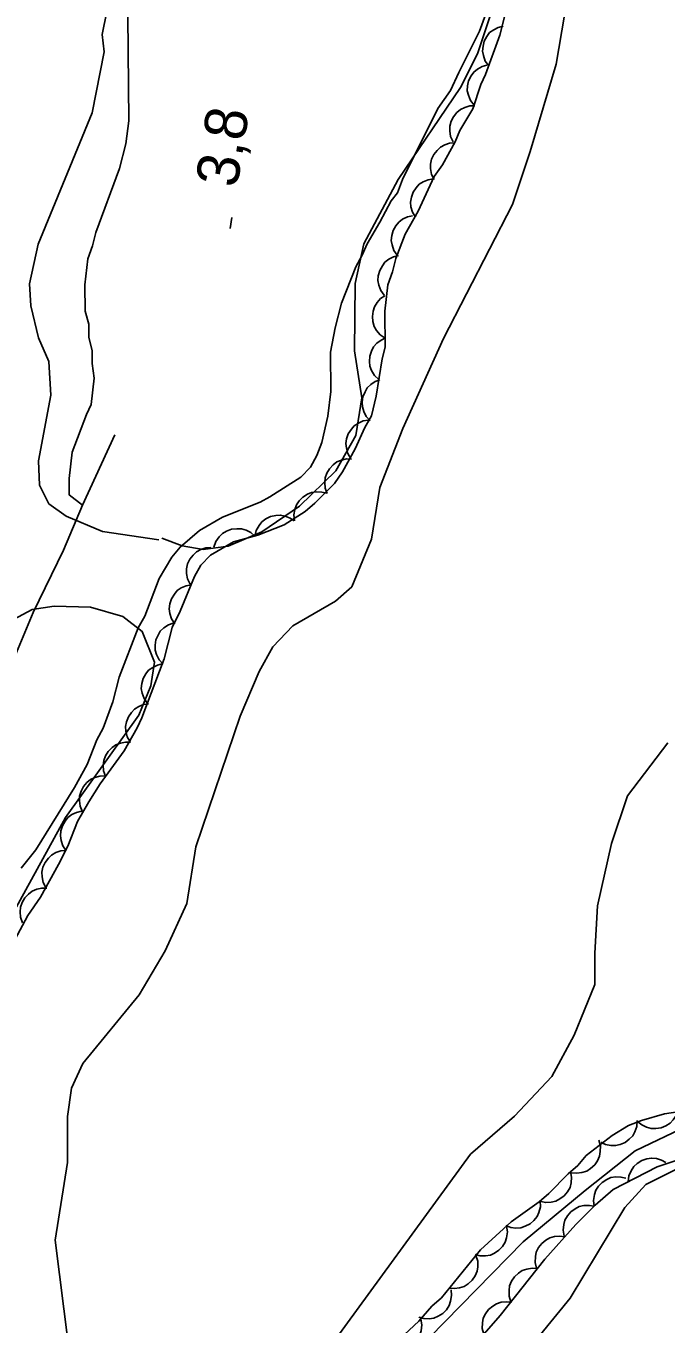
# Model space of a CAD drawing. Extents: x 282461 to 284471, y 5554090 to 5557646.
# Drawn here: x 283743.9 to 283789.4, y 5555319.8 to 5555412 of the extents above; entities that cross this region are included whole.
import ezdxf

# ---------------------------------------------------------------- set-up
doc = ezdxf.new("R2010")
doc.units = 0
for name, color, linetype in [('Niveau 1', 7, 'Continuous'), ('Niveau 2', 7, 'Continuous'), ('Niveau 22', 7, 'Continuous'), ('Niveau 3', 7, 'Continuous'), ('Niveau 44', 7, 'Continuous'), ('Niveau 7', 7, 'Continuous')]:
    doc.layers.add(name, color=color, linetype=linetype)

msp = doc.modelspace()

# ---------------------------------------------------------------- linework, layer by layer
at = {"layer": 'Niveau 1'}
for points in [[(283783.14, 5555418.61), (283781.56, 5555409.27), (283779.71, 5555403.07), (283778.46, 5555399.31), (283773.56, 5555389.8), (283770.67, 5555383.41), (283769.02, 5555379.22), (283768.44, 5555375.55), (283767.05, 5555372.17), (283765.87, 5555371.15), (283762.84, 5555369.4), (283761.44, 5555367.9), (283760.46, 5555366.14), (283759.12, 5555362.98), (283755.96, 5555353.7), (283755.32, 5555349.67), (283753.78, 5555346.33), (283751.93, 5555343.2), (283747.93, 5555338.31), (283747.14, 5555336.56), (283746.84, 5555334.55), (283746.84, 5555331.3), (283745.98, 5555325.79), (283746.9, 5555318.46)], [(283789.48, 5555361.08), (283786.61, 5555357.33), (283785.48, 5555353.95), (283784.48, 5555349.52), (283784.29, 5555346.15), (283784.31, 5555343.94), (283782.84, 5555340.33), (283781.24, 5555337.41), (283778.59, 5555334.59), (283775.48, 5555331.88), (283765.07, 5555317.64)], [(283780.44, 5555319.09), (283782.55, 5555321.65), (283786.43, 5555328.09), (283787.92, 5555329.73), (283792.36, 5555331.94), (283796.89, 5555332.28), (283799.21, 5555331.92), (283803.28, 5555330.44), (283804.08, 5555329.12), (283804, 5555326.4), (283802.31, 5555319.82)]]:
    msp.add_lwpolyline(points, dxfattribs=at)
at = {"layer": 'Niveau 2'}
for points in [[(283753.34, 5555375.49), (283749.33, 5555376.09), (283746.75, 5555377.17), (283745.52, 5555378.06), (283744.86, 5555379.38), (283744.78, 5555381.1), (283745.67, 5555385.76), (283745.53, 5555388.17), (283744.78, 5555389.84), (283744.24, 5555392.12), (283744.14, 5555393.67), (283744.77, 5555396.5), (283748.61, 5555405.81), (283749.45, 5555410.14), (283749.32, 5555411.37), (283750.68, 5555418.17)], [(283777.95, 5555416), (283775.96, 5555409.99), (283774.77, 5555407.61), (283770.33, 5555401.09), (283767.89, 5555396.51), (283767.28, 5555393.7), (283767.24, 5555388.92), (283767.76, 5555385.59), (283767.33, 5555382.91), (283765.9, 5555380.39), (283763.32, 5555377.88), (283760.65, 5555376.07), (283758.25, 5555375.06), (283756.49, 5555374.82), (283755, 5555375.07), (283753.55, 5555375.62)], [(283743.08, 5555349.18), (283746.71, 5555355.78), (283751.92, 5555363.05), (283752.77, 5555365.14), (283753.03, 5555366.81), (283752.15, 5555369), (283750.78, 5555370.06), (283748.48, 5555370.73), (283745.9, 5555370.8), (283744.33, 5555370.55), (283741.36, 5555368.96)]]:
    msp.add_lwpolyline(points, dxfattribs=at)
at = {"layer": 'Niveau 22'}
for points in [[(283750.2, 5555382.95), (283747.9, 5555377.95), (283746.56, 5555374.77), (283744.4, 5555370.33), (283741.9, 5555364.37), (283738.37, 5555352.1), (283733.72, 5555335.92), (283726.74, 5555314), (283724.74, 5555305.03), (283723.2, 5555297.46), (283722.89, 5555293.62), (283718.97, 5555278.88), (283718.11, 5555273.83)], [(283861.57, 5555341.68), (283858.39, 5555340.93), (283855.1, 5555340.42), (283852.52, 5555340.5), (283847.8, 5555340.85), (283842.97, 5555339.89), (283840.1, 5555338.96), (283836.9, 5555337.5), (283831.65, 5555335.94), (283825.53, 5555334.84), (283821.37, 5555334.21), (283813.14, 5555335.8), (283808.66, 5555336.35), (283804.55, 5555336.14), (283801.01, 5555335.82), (283795.13, 5555335.12), (283790.93, 5555333.93), (283787.16, 5555332.13), (283783.61, 5555329.3), (283779.22, 5555325.65), (283772.56, 5555318.87)]]:
    msp.add_lwpolyline(points, dxfattribs=at)
at = {"layer": 'Niveau 3'}
msp.add_line((283758.41, 5555397.59), (283758.53, 5555398.38), dxfattribs=at)
at = {"layer": 'Niveau 44'}
for points in [[(283743.11, 5555347.09), (283744.03, 5555348.84), (283744.94, 5555350.13), (283746.2, 5555352.46), (283746.88, 5555353.75), (283747.56, 5555355.5), (283748.36, 5555356.9), (283749.16, 5555358.18), (283750.88, 5555360.52), (283751.79, 5555362.16), (283752.13, 5555362.86), (283753.72, 5555367.06), (283754.27, 5555369.27), (283754.84, 5555370.44), (283755.86, 5555372.89), (283756.32, 5555373.7), (283757.01, 5555374.41), (283758.63, 5555375.36), (283760.37, 5555375.84), (283762.23, 5555376.56), (283763.73, 5555377.5), (283764.42, 5555378.09), (283765.8, 5555379.5), (283766.38, 5555380.32), (283767.29, 5555381.95), (283767.97, 5555383.47), (283768.43, 5555384.29), (283768.76, 5555385.69), (283769.2, 5555388.36), (283769.42, 5555389.18), (283769.39, 5555391.73), (283769.6, 5555393.59), (283769.94, 5555394.53), (283770.17, 5555395.46), (283770.84, 5555397.21), (283771.76, 5555398.84), (283772.9, 5555401.29), (283773.47, 5555402.11), (283774.38, 5555403.75), (283774.72, 5555404.57), (283775.64, 5555406.09), (283776.2, 5555407.83), (283776.54, 5555408.53), (283777.56, 5555411.33), (283778.67, 5555415.76)], [(283776.77, 5555409.15), (283776.52, 5555409.49), (283776.39, 5555409.88), (283776.33, 5555410.2), (283776.36, 5555410.55), (283776.45, 5555410.91), (283776.64, 5555411.24), (283776.83, 5555411.51), (283777.12, 5555411.71), (283777.44, 5555411.88), (283777.79, 5555411.97)], [(283775.72, 5555406.35), (283775.47, 5555406.68), (283775.32, 5555407.06), (283775.24, 5555407.38), (283775.26, 5555407.73), (283775.34, 5555408.09), (283775.52, 5555408.43), (283775.7, 5555408.7), (283775.97, 5555408.92), (283776.3, 5555409.1), (283776.64, 5555409.2)], [(283774.23, 5555403.76), (283774.05, 5555404.14), (283774, 5555404.54), (283774, 5555404.87), (283774.1, 5555405.21), (283774.26, 5555405.54), (283774.51, 5555405.83), (283774.75, 5555406.05), (283775.06, 5555406.2), (283775.42, 5555406.3), (283775.78, 5555406.32)], [(283772.89, 5555401.07), (283772.71, 5555401.44), (283772.63, 5555401.85), (283772.62, 5555402.18), (283772.71, 5555402.52), (283772.86, 5555402.85), (283773.1, 5555403.15), (283773.33, 5555403.38), (283773.64, 5555403.55), (283773.99, 5555403.66), (283774.35, 5555403.69)], [(283771.56, 5555398.4), (283771.34, 5555398.76), (283771.24, 5555399.15), (283771.2, 5555399.48), (283771.27, 5555399.83), (283771.39, 5555400.17), (283771.61, 5555400.49), (283771.82, 5555400.74), (283772.12, 5555400.92), (283772.47, 5555401.06), (283772.82, 5555401.12)], [(283770.26, 5555395.7), (283770.02, 5555396.05), (283769.9, 5555396.43), (283769.84, 5555396.76), (283769.88, 5555397.11), (283769.98, 5555397.46), (283770.17, 5555397.79), (283770.37, 5555398.05), (283770.65, 5555398.26), (283770.99, 5555398.42), (283771.34, 5555398.51)], [(283769.34, 5555392.86), (283769.09, 5555393.19), (283768.96, 5555393.58), (283768.89, 5555393.9), (283768.92, 5555394.25), (283769.02, 5555394.61), (283769.21, 5555394.94), (283769.39, 5555395.21), (283769.68, 5555395.42), (283770.01, 5555395.59), (283770.36, 5555395.68)], [(283769.41, 5555389.82), (283769.06, 5555390.05), (283768.8, 5555390.37), (283768.63, 5555390.65), (283768.54, 5555390.99), (283768.5, 5555391.35), (283768.56, 5555391.73), (283768.64, 5555392.05), (283768.83, 5555392.34), (283769.08, 5555392.62), (283769.38, 5555392.82)], [(283768.96, 5555386.87), (283768.65, 5555387.16), (283768.45, 5555387.51), (283768.33, 5555387.82), (283768.29, 5555388.17), (283768.32, 5555388.54), (283768.45, 5555388.9), (283768.58, 5555389.2), (283768.82, 5555389.46), (283769.12, 5555389.68), (283769.44, 5555389.83)], [(283768.35, 5555383.94), (283768.06, 5555384.25), (283767.89, 5555384.61), (283767.79, 5555384.93), (283767.78, 5555385.28), (283767.83, 5555385.64), (283767.98, 5555386), (283768.14, 5555386.28), (283768.39, 5555386.52), (283768.7, 5555386.73), (283769.04, 5555386.86)], [(283766.98, 5555381.26), (283766.76, 5555381.62), (283766.66, 5555382.01), (283766.62, 5555382.34), (283766.67, 5555382.68), (283766.79, 5555383.03), (283767.01, 5555383.35), (283767.21, 5555383.6), (283767.51, 5555383.79), (283767.85, 5555383.94), (283768.21, 5555384)], [(283765.29, 5555378.78), (283765.14, 5555379.17), (283765.12, 5555379.58), (283765.14, 5555379.91), (283765.26, 5555380.24), (283765.45, 5555380.55), (283765.72, 5555380.83), (283765.97, 5555381.03), (283766.3, 5555381.16), (283766.66, 5555381.24), (283767.02, 5555381.23)], [(283762.97, 5555376.85), (283762.92, 5555377.27), (283763, 5555377.66), (283763.1, 5555377.98), (283763.3, 5555378.27), (283763.56, 5555378.53), (283763.89, 5555378.73), (283764.18, 5555378.87), (283764.53, 5555378.91), (283764.9, 5555378.89), (283765.25, 5555378.8)], [(283760.15, 5555375.76), (283760.25, 5555376.16), (283760.45, 5555376.52), (283760.65, 5555376.78), (283760.93, 5555376.98), (283761.26, 5555377.15), (283761.64, 5555377.22), (283761.96, 5555377.25), (283762.31, 5555377.18), (283762.65, 5555377.04), (283762.95, 5555376.84)], [(283757.25, 5555374.98), (283757.39, 5555375.38), (283757.62, 5555375.71), (283757.85, 5555375.95), (283758.15, 5555376.12), (283758.5, 5555376.25), (283758.88, 5555376.29), (283759.21, 5555376.29), (283759.54, 5555376.18), (283759.87, 5555376.01), (283760.14, 5555375.78)], [(283755.55, 5555372.34), (283755.37, 5555372.72), (283755.3, 5555373.12), (283755.29, 5555373.45), (283755.38, 5555373.79), (283755.53, 5555374.13), (283755.77, 5555374.42), (283756.01, 5555374.65), (283756.32, 5555374.81), (283756.67, 5555374.92), (283757.03, 5555374.95)], [(283754.47, 5555369.54), (283754.24, 5555369.89), (283754.12, 5555370.28), (283754.07, 5555370.61), (283754.12, 5555370.96), (283754.23, 5555371.31), (283754.44, 5555371.63), (283754.64, 5555371.89), (283754.93, 5555372.08), (283755.27, 5555372.24), (283755.62, 5555372.31)], [(283753.63, 5555366.68), (283753.35, 5555366.99), (283753.17, 5555367.36), (283753.08, 5555367.67), (283753.07, 5555368.02), (283753.13, 5555368.39), (283753.28, 5555368.74), (283753.44, 5555369.02), (283753.7, 5555369.26), (283754.01, 5555369.47), (283754.35, 5555369.59)], [(283752.52, 5555363.89), (283752.28, 5555364.23), (283752.15, 5555364.62), (283752.09, 5555364.94), (283752.13, 5555365.29), (283752.23, 5555365.65), (283752.42, 5555365.98), (283752.61, 5555366.24), (283752.9, 5555366.44), (283753.23, 5555366.61), (283753.58, 5555366.69)], [(283751.3, 5555361.15), (283751.09, 5555361.51), (283751, 5555361.91), (283750.97, 5555362.24), (283751.04, 5555362.58), (283751.17, 5555362.93), (283751.39, 5555363.24), (283751.61, 5555363.48), (283751.91, 5555363.66), (283752.25, 5555363.8), (283752.61, 5555363.85)], [(283749.55, 5555358.71), (283749.41, 5555359.1), (283749.39, 5555359.51), (283749.42, 5555359.84), (283749.55, 5555360.17), (283749.74, 5555360.48), (283750.02, 5555360.75), (283750.27, 5555360.95), (283750.6, 5555361.07), (283750.97, 5555361.14), (283751.33, 5555361.13)], [(283747.92, 5555356.2), (283747.75, 5555356.58), (283747.7, 5555356.98), (283747.7, 5555357.31), (283747.81, 5555357.65), (283747.98, 5555357.98), (283748.23, 5555358.26), (283748.47, 5555358.48), (283748.79, 5555358.63), (283749.15, 5555358.73), (283749.51, 5555358.74)], [(283746.76, 5555353.43), (283746.52, 5555353.78), (283746.4, 5555354.16), (283746.34, 5555354.49), (283746.38, 5555354.84), (283746.48, 5555355.19), (283746.68, 5555355.52), (283746.87, 5555355.78), (283747.16, 5555355.99), (283747.49, 5555356.15), (283747.84, 5555356.23)], [(283745.31, 5555350.81), (283745.11, 5555351.18), (283745.04, 5555351.58), (283745.02, 5555351.91), (283745.1, 5555352.25), (283745.25, 5555352.59), (283745.49, 5555352.89), (283745.71, 5555353.12), (283746.02, 5555353.29), (283746.37, 5555353.41), (283746.73, 5555353.44)], [(283743.65, 5555348.31), (283743.51, 5555348.7), (283743.48, 5555349.1), (283743.5, 5555349.43), (283743.62, 5555349.76), (283743.81, 5555350.08), (283744.08, 5555350.35), (283744.33, 5555350.56), (283744.66, 5555350.69), (283745.02, 5555350.77), (283745.38, 5555350.76)], [(283790.99, 5555335.01), (283789.24, 5555334.76), (283787.61, 5555334.27), (283786.69, 5555333.91), (283785.53, 5555333.21), (283783.68, 5555331.79), (283783.1, 5555331.09), (283782.41, 5555330.5), (283781.03, 5555329.09), (283780.34, 5555328.5), (283778.37, 5555327.08), (283776.18, 5555325.09), (283773.42, 5555321.69), (283772.73, 5555321.1), (283771.81, 5555320.04), (283770.42, 5555318.75)], [(283790.23, 5555335.06), (283790.1, 5555334.66), (283789.87, 5555334.32), (283789.65, 5555334.08), (283789.35, 5555333.89), (283789.01, 5555333.76), (283788.63, 5555333.71), (283788.3, 5555333.7), (283787.97, 5555333.8), (283787.63, 5555333.97), (283787.35, 5555334.19)], [(283787.31, 5555334.28), (283787.28, 5555333.86), (283787.15, 5555333.48), (283786.99, 5555333.19), (283786.75, 5555332.94), (283786.45, 5555332.72), (283786.09, 5555332.58), (283785.78, 5555332.49), (283785.43, 5555332.51), (283785.07, 5555332.58), (283784.74, 5555332.73)], [(283784.58, 5555332.87), (283784.7, 5555332.47), (283784.69, 5555332.07), (283784.64, 5555331.74), (283784.5, 5555331.42), (283784.29, 5555331.12), (283784, 5555330.87), (283783.73, 5555330.68), (283783.39, 5555330.58), (283783.02, 5555330.53), (283782.66, 5555330.56)], [(283765.23, 5555306.27), (283777.58, 5555320.44), (283780.74, 5555324.44), (283782.96, 5555326.9), (283784.33, 5555328.26), (283785.61, 5555329.38), (283788.74, 5555330.99), (283791.89, 5555332.06)], [(283786.67, 5555329.93), (283786.72, 5555330.34), (283786.89, 5555330.71), (283787.06, 5555331), (283787.32, 5555331.23), (283787.63, 5555331.43), (283788, 5555331.55), (283788.32, 5555331.61), (283788.67, 5555331.57), (283789.03, 5555331.47), (283789.34, 5555331.3)], [(283782.57, 5555330.66), (283782.65, 5555330.25), (283782.61, 5555329.85), (283782.54, 5555329.53), (283782.37, 5555329.22), (283782.13, 5555328.93), (283781.82, 5555328.71), (283781.54, 5555328.55), (283781.19, 5555328.47), (283780.82, 5555328.45), (283780.47, 5555328.52)], [(283784.25, 5555328.19), (283784.2, 5555328.6), (283784.27, 5555329.01), (283784.37, 5555329.32), (283784.56, 5555329.61), (283784.82, 5555329.88), (283785.15, 5555330.08), (283785.44, 5555330.22), (283785.79, 5555330.27), (283786.16, 5555330.26), (283786.51, 5555330.17)], [(283780.43, 5555328.56), (283780.44, 5555328.15), (283780.33, 5555327.75), (283780.21, 5555327.45), (283779.98, 5555327.18), (283779.7, 5555326.94), (283779.36, 5555326.77), (283779.05, 5555326.66), (283778.7, 5555326.64), (283778.33, 5555326.69), (283777.99, 5555326.81)], [(283782.12, 5555326.07), (283782.05, 5555326.48), (283782.09, 5555326.89), (283782.17, 5555327.21), (283782.35, 5555327.51), (283782.59, 5555327.79), (283782.9, 5555328.01), (283783.18, 5555328.17), (283783.53, 5555328.24), (283783.9, 5555328.25), (283784.25, 5555328.19)], [(283778.03, 5555326.77), (283778.09, 5555326.36), (283778.03, 5555325.95), (283777.93, 5555325.64), (283777.74, 5555325.34), (283777.49, 5555325.07), (283777.17, 5555324.86), (283776.88, 5555324.72), (283776.53, 5555324.66), (283776.16, 5555324.67), (283775.81, 5555324.75)], [(283780.16, 5555323.8), (283780.06, 5555324.2), (283780.08, 5555324.61), (283780.14, 5555324.93), (283780.3, 5555325.25), (283780.53, 5555325.54), (283780.83, 5555325.78), (283781.1, 5555325.95), (283781.44, 5555326.04), (283781.81, 5555326.07), (283782.17, 5555326.02)], [(283775.86, 5555324.7), (283775.98, 5555324.3), (283775.98, 5555323.89), (283775.94, 5555323.57), (283775.8, 5555323.25), (283775.59, 5555322.94), (283775.3, 5555322.69), (283775.03, 5555322.5), (283774.7, 5555322.39), (283774.33, 5555322.34), (283773.97, 5555322.37)], [(283778.34, 5555321.4), (283778.21, 5555321.8), (283778.21, 5555322.21), (283778.25, 5555322.54), (283778.39, 5555322.86), (283778.59, 5555323.17), (283778.88, 5555323.43), (283779.14, 5555323.62), (283779.48, 5555323.73), (283779.84, 5555323.79), (283780.2, 5555323.76)], [(283774.09, 5555322.26), (283774.13, 5555321.85), (283774.06, 5555321.45), (283773.96, 5555321.13), (283773.76, 5555320.84), (283773.5, 5555320.58), (283773.17, 5555320.38), (283772.87, 5555320.25), (283772.53, 5555320.2), (283772.16, 5555320.22), (283771.81, 5555320.31)], [(283776.41, 5555319.1), (283776.31, 5555319.51), (283776.32, 5555319.91), (283776.38, 5555320.24), (283776.53, 5555320.55), (283776.75, 5555320.85), (283777.05, 5555321.1), (283777.32, 5555321.27), (283777.66, 5555321.37), (283778.03, 5555321.41), (283778.39, 5555321.37)], [(283771.95, 5555320.17), (283772.01, 5555319.76), (283771.96, 5555319.35), (283771.87, 5555319.04), (283771.68, 5555318.74), (283771.43, 5555318.47), (283771.11, 5555318.26), (283770.82, 5555318.11), (283770.47, 5555318.05), (283770.1, 5555318.05), (283769.75, 5555318.13)]]:
    msp.add_lwpolyline(points, dxfattribs=at)
at = {"layer": 'Niveau 7'}
for points in [[(283743.56, 5555352.19), (283744.59, 5555353.48), (283747.34, 5555357.92), (283748.25, 5555359.56), (283748.93, 5555361.31), (283749.39, 5555362.13), (283750.07, 5555364), (283750.51, 5555365.75), (283751.87, 5555369.25), (283752.33, 5555370.07), (283753.35, 5555372.75), (283754.26, 5555374.27), (283754.84, 5555374.98), (283756.23, 5555376.16), (283757.85, 5555377.1), (283760.52, 5555378.18), (283761.21, 5555378.54), (283763.41, 5555379.95), (283764.1, 5555380.66), (283764.56, 5555381.48), (283764.9, 5555382.41), (283765.34, 5555384.28), (283765.56, 5555386.02), (283765.53, 5555388.81), (283765.86, 5555390.56), (283766.3, 5555392.31), (283767.32, 5555394.88), (283767.78, 5555395.7), (283768.12, 5555396.52), (283769.04, 5555398.04), (283769.83, 5555399.56), (283770.29, 5555400.14), (283770.63, 5555401.08), (283773.14, 5555406.11), (283774.06, 5555407.39), (283774.63, 5555408.68), (283776.11, 5555411.6), (283777.13, 5555414.4)], [(283751.13, 5555412.69), (283751.21, 5555405.25), (283751, 5555403.62), (283750.55, 5555401.87), (283748.86, 5555397.32), (283748.63, 5555396.38), (283748.29, 5555395.45), (283748.08, 5555393.59), (283748.1, 5555391.73), (283748.35, 5555390.8), (283748.36, 5555389.87), (283748.6, 5555388.94), (283748.61, 5555388.01), (283748.74, 5555386.97), (283748.53, 5555385.1), (283748.19, 5555384.4), (283747.17, 5555381.72), (283746.96, 5555379.85), (283746.97, 5555378.69), (283747.9, 5555377.95)]]:
    msp.add_lwpolyline(points, dxfattribs=at)

# ---------------------------------------------------------------- texts
at = {"layer": 'Niveau 3'}
msp.add_text('3,8  ', height=3, rotation=81.09575, dxfattribs=at).set_placement((283758.89, 5555400.43))

doc.saveas('drawing.dxf')
